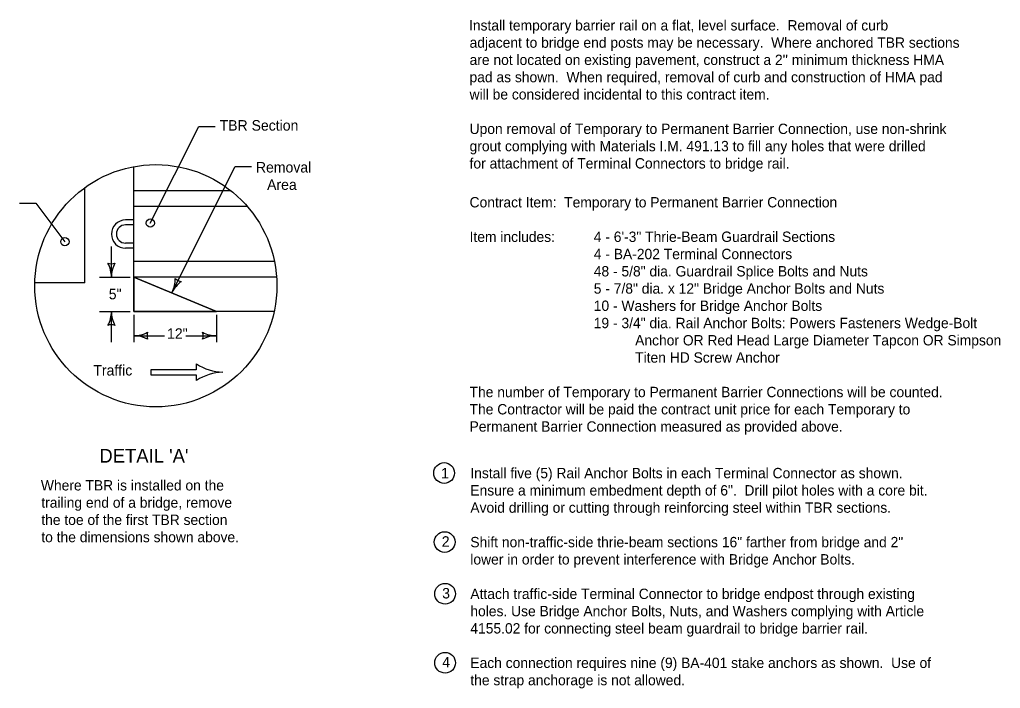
# Model space of a CAD drawing. Extents: x -2137026 to -2131464, y -2138478 to -2136524.
# Drawn here: x -2135534 to -2134113, y -2137493 to -2136524 of the extents above; entities that cross this region are included whole.
import ezdxf

# ---------------------------------------------------------------- set-up
doc = ezdxf.new("R2010")
doc.units = 0
for name, color, linetype in [('Level 2', 7, 'Continuous'), ('Level 3', 7, 'Continuous'), ('Level 41', 7, 'Continuous'), ('Level 9', 7, 'Continuous')]:
    doc.layers.add(name, color=color, linetype=linetype)

msp = doc.modelspace()

# ---------------------------------------------------------------- linework, layer by layer
at = {"layer": 'Level 2'}
for p, q in [((-2135344.9, -2136818.4), (-2135274.5, -2136678.4)), ((-2135274.5, -2136678.4), (-2135250.9, -2136678.4)), ((-2135368.8, -2136946.6), (-2135368.8, -2136736.6)), ((-2135313.4, -2136918.7), (-2135221.9, -2136736.4)), ((-2135221.9, -2136736.4), (-2135198.3, -2136736.4)), ((-2135227.6, -2136771.9), (-2135368.8, -2136771.9)), ((-2135534.3, -2136789.4), (-2135510.7, -2136789.4)), ((-2135510.7, -2136789.4), (-2135468.7, -2136845.4)), ((-2135204.2, -2136794.3), (-2135368.8, -2136794.3)), ((-2135401.3, -2136896.7), (-2135401.3, -2136852.3)), ((-2135164.9, -2136874.2), (-2135368.8, -2136874.2)), ((-2135418.6, -2136896.7), (-2135374.3, -2136896.7)), ((-2135161.8, -2136896.7), (-2135368.8, -2136896.7)), ((-2135418.6, -2136946.6), (-2135374.3, -2136946.6)), ((-2135401.3, -2136991), (-2135401.3, -2136946.6)), ((-2135165.4, -2136946.6), (-2135368.8, -2136946.6)), ((-2135368.8, -2136951.6), (-2135368.8, -2136990.8)), ((-2135249, -2136951.6), (-2135249, -2136990.8)), ((-2135368.8, -2136981.7), (-2135324.4, -2136981.7)), ((-2135293.4, -2136981.7), (-2135249, -2136981.7))]:
    msp.add_line(p, q, dxfattribs=at)
for centre in [(-2134919, -2137180.6), (-2134918.2, -2137280.6), (-2134917.6, -2137355.6), (-2134917.6, -2137455.6)]:
    msp.add_circle(centre, 15, dxfattribs=at)
for centre, radius, start, end in [((-2135401.3, -2136861), 16.4, 252.2666, 287.7334), ((-2135443.8, -2136896.7), 42.5, 0, 28.0725), ((-2135401.3, -2136861), 16.4, 252.2666, 287.7334), ((-2135443.8, -2136896.7), 42.5, 0, 28.0725), ((-2135358.8, -2136896.7), 42.5, 151.9275, 180), ((-2135358.8, -2136896.7), 42.5, 151.9275, 180), ((-2135351.3, -2136899.5), 42.5, 333.1429, 1.2154), ((-2135297.3, -2136886.9), 16.4, 225.4095, 260.8762), ((-2135275.5, -2136937.9), 42.5, 125.0704, 153.1429), ((-2135443.8, -2136946.6), 42.5, 331.9275, 0), ((-2135443.8, -2136946.6), 42.5, 331.9275, 0), ((-2135358.8, -2136946.6), 42.5, 180, 208.0725), ((-2135358.8, -2136946.6), 42.5, 180, 208.0725), ((-2135401.3, -2136982.2), 16.4, 72.2666, 107.7334), ((-2135401.3, -2136982.2), 16.4, 72.2666, 107.7334), ((-2135368.8, -2136939.2), 42.5, 270, 298.0725), ((-2135368.8, -2136939.2), 42.5, 270, 298.0725), ((-2135368.8, -2137024.2), 42.5, 61.9275, 90), ((-2135368.8, -2137024.2), 42.5, 61.9275, 90), ((-2135333.2, -2136981.7), 16.4, 162.2666, 197.7334), ((-2135333.2, -2136981.7), 16.4, 162.2666, 197.7334), ((-2135284.7, -2136981.7), 16.4, 342.2667, 17.7334), ((-2135249, -2136939.2), 42.5, 241.9275, 270), ((-2135284.7, -2136981.7), 16.4, 342.2667, 17.7334), ((-2135249, -2136939.2), 42.5, 241.9275, 270), ((-2135249, -2137024.2), 42.5, 90, 118.0725), ((-2135249, -2137024.2), 42.5, 90, 118.0725)]:
    msp.add_arc(centre, radius, start, end, dxfattribs=at)
at = {"layer": 'Level 41'}
for p, q in [((-2135368.8, -2136813.9), (-2135380.8, -2136813.9)), ((-2135368.8, -2136821.1), (-2135380.8, -2136821.1)), ((-2135368.8, -2136847.4), (-2135380.8, -2136847.4)), ((-2135368.8, -2136854.6), (-2135380.8, -2136854.6))]:
    msp.add_line(p, q, dxfattribs=at)
for radius in [20.4, 13.2]:
    msp.add_arc((-2135380.8, -2136834.3), radius, 90, 270, dxfattribs=at)
at = {"layer": 'Level 9'}
for p, q in [((-2135439.6, -2136905), (-2135439.6, -2136766.9)), ((-2135439.6, -2136905), (-2135512.4, -2136905)), ((-2135278.2, -2137022.5), (-2135278.2, -2137030.9)), ((-2135278.2, -2137030.9), (-2135344.2, -2137030.9)), ((-2135344.2, -2137030.9), (-2135344.2, -2137038.1)), ((-2135344.2, -2137038.1), (-2135278.2, -2137038.1)), ((-2135278.2, -2137038.1), (-2135278.2, -2137046.5)), ((-2135239.9, -2137034.5), (-2135239.9, -2137034.5))]:
    msp.add_line(p, q, dxfattribs=at)
msp.add_lwpolyline([(-2135368.8, -2136946.6), (-2135249, -2136946.6), (-2135368.8, -2136896.7), (-2135368.8, -2136946.6)], dxfattribs=at)
msp.add_lwpolyline([(-2135368.8, -2136896.7), (-2135249, -2136946.6), (-2135368.8, -2136946.6)], close=True, dxfattribs=at)
for centre, radius in [((-2135336.9, -2136909.2), 175.5), ((-2135344.9, -2136818.4), 5.96), ((-2135468.7, -2136845.4), 5.96)]:
    msp.add_circle(centre, radius, dxfattribs=at)
for centre, start, end in [((-2135236.7, -2136957.2), 237.618, 267.648), ((-2135236.7, -2137111.8), 92.352, 122.382)]:
    msp.add_arc(centre, 77.4, start, end, dxfattribs=at)

# ---------------------------------------------------------------- texts
at = {"layer": 'Level 2'}
for s, p in [('1', (-2134923.4, -2137188.5)), ('2', (-2134922.4, -2137287.4)), ('3', (-2134921.8, -2137362.4)), ('4', (-2134921.8, -2137462.4))]:
    msp.add_text(s, height=15.2, dxfattribs=at).set_placement(p)
at = {"layer": 'Level 3'}
for s, height, p in [('TBR Section', 15.2, (-2135244.4, -2136684.4)), ('Removal', 15.2, (-2135191.8, -2136745.1)), ('Area', 15.2, (-2135175.6, -2136770.3)), ('5"', 15.2, (-2135405.1, -2136928.8)), ('12"', 15.2, (-2135320.6, -2136986.1)), ('Traffic', 15.2, (-2135427.5, -2137039.3)), ("DETAIL 'A'", 20, (-2135418.7, -2137165.6))]:
    msp.add_text(s, height=height, dxfattribs=at).set_placement(p)
at = {"layer": 'Level 9'}
for s, p in [('Install temporary barrier rail on a flat, level surface.  Removal of curb ', (-2134882.9, -2136539.3)), ('adjacent to bridge end posts may be necessary.  Where anchored TBR sections ', (-2134882.1, -2136564.3)), ("are not located on existing pavement, construct a 2'' minimum thickness HMA ", (-2134882.1, -2136589.3)), ('pad as shown.  When required, removal of curb and construction of HMA pad ', (-2134882.2, -2136614.3)), ('will be considered incidental to this contract item.', (-2134882.1, -2136639.3)), ('Upon removal of Temporary to Permanent Barrier Connection, use non-shrink ', (-2134882.1, -2136689.3)), ('grout complying with Materials I.M. 491.13 to fill any holes that were drilled ', (-2134882.1, -2136714.3)), ('for attachment of Terminal Connectors to bridge rail.', (-2134882.1, -2136739.3)), ('Contract Item:  Temporary to Permanent Barrier Connection', (-2134882.1, -2136795.7)), ('Item includes:', (-2134882.1, -2136845.7)), ('4 - 6\'-3" Thrie-Beam Guardrail Sections', (-2134702.1, -2136845.7)), ('4 - BA-202 Terminal Connectors', (-2134702.1, -2136870.7)), ('48 - 5/8" dia. Guardrail Splice Bolts and Nuts', (-2134702.1, -2136895.7)), ('5 - 7/8" dia. x 12" Bridge Anchor Bolts and Nuts', (-2134702.1, -2136920.7)), ('10 - Washers for Bridge Anchor Bolts', (-2134702.1, -2136945.7)), ('19 - 3/4" dia. Rail Anchor Bolts: Powers Fasteners Wedge-Bolt', (-2134702.1, -2136970.7)), ('Anchor OR Red Head Large Diameter Tapcon OR Simpson', (-2134642.1, -2136995.7)), ('Titen HD Screw Anchor', (-2134642.1, -2137020.7)), ('The number of Temporary to Permanent Barrier Connections will be counted.  ', (-2134882.1, -2137070.7)), ('The Contractor will be paid the contract unit price for each Temporary to ', (-2134882.1, -2137095.7)), ('Permanent Barrier Connection measured as provided above.', (-2134882.1, -2137120.7)), ('Install five (5) Rail Anchor Bolts in each Terminal Connector as shown.  ', (-2134881, -2137188.2)), ('Where TBR is installed on the ', (-2135503.5, -2137205.9)), ('Ensure a minimum embedment depth of 6".  Drill pilot holes with a core bit.  ', (-2134881, -2137213.2)), ('trailing end of a bridge, remove ', (-2135502.9, -2137230.9)), ('Avoid drilling or cutting through reinforcing steel within TBR sections.', (-2134881, -2137238.2)), ('the toe of the first TBR section ', (-2135502.9, -2137255.9)), ('to the dimensions shown above.', (-2135502.9, -2137280.9)), ('Shift non-traffic-side thrie-beam sections 16" farther from bridge and 2" ', (-2134881, -2137288.2)), ('lower in order to prevent interference with Bridge Anchor Bolts.', (-2134881, -2137313.2)), ('Attach traffic-side Terminal Connector to bridge endpost through existing ', (-2134881, -2137363.2)), ('holes. Use Bridge Anchor Bolts, Nuts, and Washers complying with Article ', (-2134881, -2137388.2)), ('4155.02 for connecting steel beam guardrail to bridge barrier rail.', (-2134881, -2137413.2)), ('Each connection requires nine (9) BA-401 stake anchors as shown.  Use of ', (-2134881, -2137463.2)), ('the strap anchorage is not allowed.', (-2134881, -2137488.2))]:
    msp.add_text(s, height=15, dxfattribs=at).set_placement(p)

doc.saveas('drawing.dxf')
